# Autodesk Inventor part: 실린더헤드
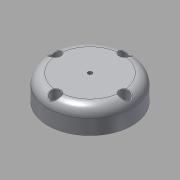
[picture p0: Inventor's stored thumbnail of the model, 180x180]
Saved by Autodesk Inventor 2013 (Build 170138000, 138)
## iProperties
Created: 2016-11
Part Number: 실린더헤드
Material: 알루미늄 6061
Document SubType Name: Modeling
Designer: mduedu
Density: 2.71 g/cm^3
Mass: 284.816 g
Surface Area: 227.25 cm^2
Volume: 105.098 cm^3
Author: mduedu
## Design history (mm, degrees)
sketch "스케치1"
  geometry: C1 r 42.5 at (0, 0); 1 further point
  constraints: 1 centre point, 1 coincident
  dimensions: "d0" = 85 diameter of C1
extrude "돌출1" new body sketch "스케치1" distance "d1" = 25; taper "d2" = 0 deg
fillet "모깎기1" dims "d3" = 10
sketch "스케치2"
  geometry: C1 r 30 at (0, 0); 1 further point
  constraints: 1 centre point, 1 coincident
  dimensions: "d4" = 60 diameter of C1
extrude "돌출2" join sketch "스케치2" distance "d5" = 5; taper "d6" = 0 deg
sketch "스케치3"
  geometry: C1 r 25 at (0, 0); 1 further point
  constraints: 1 centre point, 1 coincident
  dimensions: "d7" = 50 diameter of C1
extrude "돌출3" cut sketch "스케치3" distance "d8" = 20; taper "d9" = 0 deg
hole "구멍1" diameter "d12" = 4.134; stored, may be unused: countersink angle "d16" = 90 deg, drill point angle "d18" = 118 deg; dims "d10" = 10, "d11" = 10, "d13" = 6, "d14" = 4, "d15" = 2, "d17" = 8
chamfer "모따기1" distance "d19" = 1; stored, may be unused: second distance "d20" = 2, angle "d21" = 45 deg
fillet "모깎기2" dims "d22" = 3
sketch "스케치4"
  geometry: C1 r 17.5 at (0, 0); 1 further point
  constraints: 1 centre point, 1 coincident
  dimensions: "d23" = 35 diameter of C1
extrude "돌출4" cut sketch "스케치4" distance "d24" = 2; taper "d25" = 0 deg
fillet "모깎기3" dims "d26" = 0.5
sketch "스케치5" dims "d32" = 70
  geometry: C1 r 5 at (0, 35); 3 further points
  constraints: 2 coincident, 2 vertical alignment, 1 centre point, 2 other
  dimensions: "d33" = 10 diameter of C1
extrude "돌출5" cut sketch "스케치5" distance "d34" = 10; taper "d35" = 0 deg
sketch "스케치6" dims "d39" = 70
  geometry: 6 further points
  constraints: 2 vertical alignment, 1 coincident, 7 other
  dimensions: "d42" = 360 deg dimension on point (0, -35) point (0, 0) (derived)
sketch "스케치7"
  geometry: 4 further points
  constraints: 4 other
hole "구멍2" sketch "스케치7" at (0, 70), (-35, 35), (35, 35), (0, 0) diameter "d44" = 5.5; stored, may be unused: countersink angle "d48" = 90 deg, drill point angle "d50" = 0 deg; dims "d45" = 6, "d46" = 4, "d47" = 2, "d49" = 8
fillet "모깎기4" dims "d51" = 0.5
node "솔리드1"
pattern_circular "원형 패턴1" dims angle "d37" = 360 deg
